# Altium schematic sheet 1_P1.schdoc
size 309 x 223 mm; Symbol: Sheet-Symbol_A4; Device: Sheet-Symbol_A4; @Page Name: P1; @Create Date: 2023-03-08; @Page Count: 2; @Page No: 1; @Project Name: flatbox; @Schematic Name: Schematic1; @Update Date: 2023-03-20; Company: 嘉立创EDA; Page Size: A4; Version: V1.0
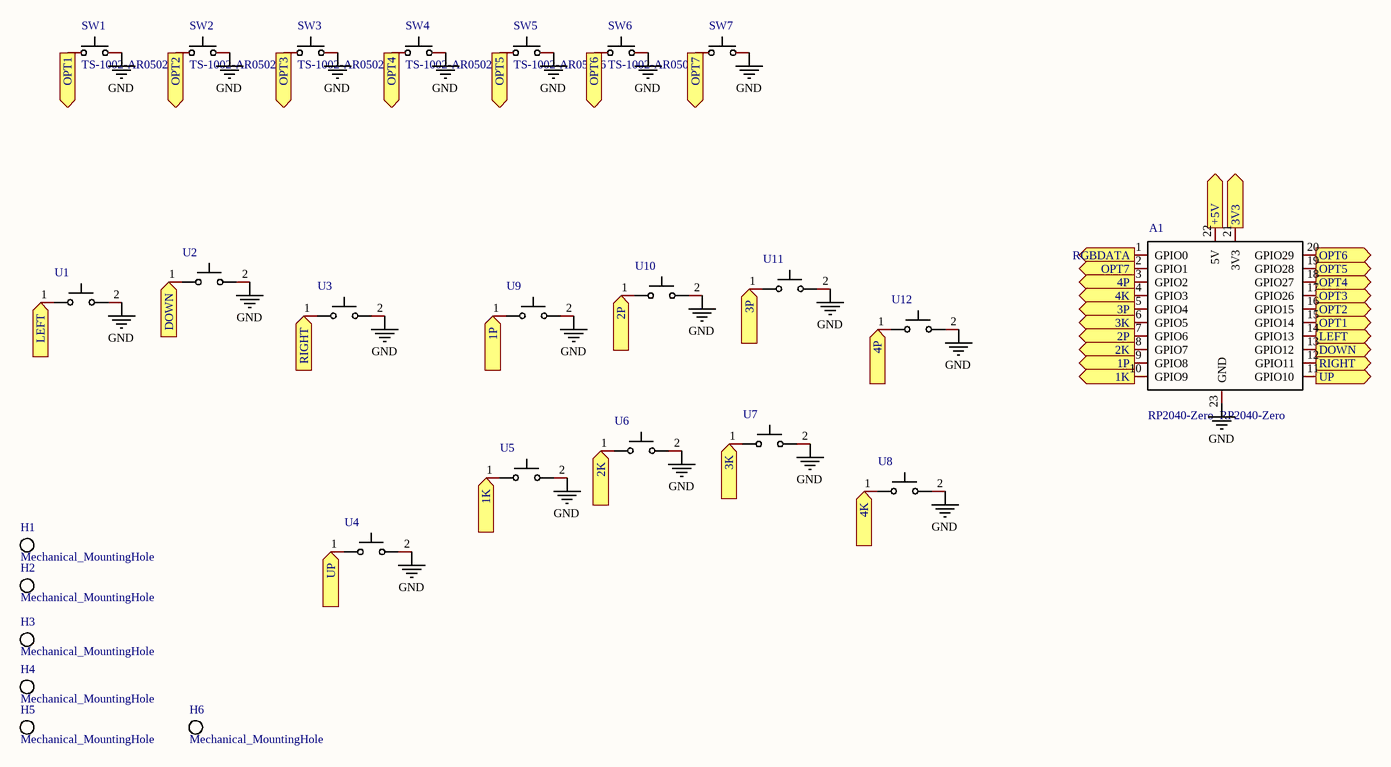
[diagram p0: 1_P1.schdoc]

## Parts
A1  RP2040-Zero_RP2040-Zero  [RP2040-Zero:RP2040-Zero]
H1  Mechanical_MountingHole  [MountingHole:MountingHole_6.4mm_M6]
H2  Mechanical_MountingHole  [MountingHole:MountingHole_6.4mm_M6]
H3  Mechanical_MountingHole  [MountingHole:MountingHole_6.4mm_M6]
H4  Mechanical_MountingHole  [MountingHole:MountingHole_6.4mm_M6]
H5  Mechanical_MountingHole  [MountingHole:MountingHole_6.4mm_M6]
H6  Mechanical_MountingHole  [MountingHole:MountingHole_6.4mm_M6]
SW1  TS-1002-AR05026  [SW-TH_4P-L6.0-W6.0-P4.50-LS6.5]
SW2  TS-1002-AR05026  [SW-TH_4P-L6.0-W6.0-P4.50-LS6.5]
SW3  TS-1002-AR05026  [SW-TH_4P-L6.0-W6.0-P4.50-LS6.5]
SW4  TS-1002-AR05026  [SW-TH_4P-L6.0-W6.0-P4.50-LS6.5]
SW5  TS-1002-AR05026  [SW-TH_4P-L6.0-W6.0-P4.50-LS6.5]
SW6  TS-1002-AR05026  [SW-TH_4P-L6.0-W6.0-P4.50-LS6.5]
SW7  TS-1002-AR05026  [SW-TH_4P-L6.0-W6.0-P4.50-LS6.5]  (value not drawn)
U1  CPG135001D02  [Kailh_socket_MX-ChocV1]  (value not drawn)
U2  CPG135001D02  [Kailh_socket_MX-ChocV1]  (value not drawn)
U3  CPG135001D02  [Kailh_socket_MX-ChocV1]  (value not drawn)
U4  CPG135001D02  [Kailh_socket_MX-ChocV1]  (value not drawn)
U5  CPG135001D02  [Kailh_socket_MX-ChocV1]  (value not drawn)
U6  CPG135001D02  [Kailh_socket_MX-ChocV1]  (value not drawn)
U7  CPG135001D02  [Kailh_socket_MX-ChocV1]  (value not drawn)
U8  CPG135001D02  [Kailh_socket_MX-ChocV1]  (value not drawn)
U9  CPG135001D02  [Kailh_socket_MX-ChocV1]  (value not drawn)
U10  CPG135001D02  [Kailh_socket_MX-ChocV1]  (value not drawn)
U11  CPG135001D02  [Kailh_socket_MX-ChocV1]  (value not drawn)
U12  CPG135001D02  [Kailh_socket_MX-ChocV1]  (value not drawn)

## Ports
1K (in), 1K (out), 1P (in), 1P (out), 2K (in), 2K (out), 2P (in), 2P (out), 3K (in), 3K (out), 3P (in), 3P (out), 3V3 (out), 4K (in), 4K (out), 4P (in), 4P (out), +5V (out), DOWN (in), DOWN (out), LEFT (in), LEFT (out), OPT1 (out), OPT2 (out), OPT3 (out), OPT4 (out), OPT5 (out), OPT6 (out), OPT7 (out), RGBDATA (out), RIGHT (in), RIGHT (out), UP (in), UP (out)

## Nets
GND: A1.23(GND) SW1.2 SW2.2 SW3.2 SW4.2 SW5.2 SW6.2 SW7.2 U1.2 U2.2 U3.2 U4.2 U5.2 U6.2 U7.2 U8.2 U9.2 U10.2 U11.2 U12.2
1K: A1.10(GPIO9) U5.1 ; port 1K
1P: A1.9(GPIO8) U9.1 ; port 1P
2K: A1.8(GPIO7) U6.1 ; port 2K
2P: A1.7(GPIO6) U10.1 ; port 2P
3K: A1.6(GPIO5) U7.1 ; port 3K
3P: A1.5(GPIO4) U11.1 ; port 3P
3V3: A1.21(3V3) ; port 3V3
4K: A1.4(GPIO3) U8.1 ; port 4K
4P: A1.3(GPIO2) U12.1 ; port 4P
+5V: A1.22(5V) ; port +5V
DOWN: A1.13(GPIO12) U2.1 ; port DOWN
LEFT: A1.14(GPIO13) U1.1 ; port LEFT
OPT1: A1.15(GPIO14) SW1.1 ; port OPT1
OPT2: A1.16(GPIO15) SW2.1 ; port OPT2
OPT3: A1.17(GPIO26) SW3.1 ; port OPT3
OPT4: A1.18(GPIO27) SW4.1 ; port OPT4
OPT5: A1.19(GPIO28) SW5.1 ; port OPT5
OPT6: A1.20(GPIO29) SW6.1 ; port OPT6
OPT7: A1.2(GPIO1) SW7.1 ; port OPT7
RGBDATA: A1.1(GPIO0) ; port RGBDATA
RIGHT: A1.12(GPIO11) U3.1 ; port RIGHT
UP: A1.11(GPIO10) U4.1 ; port UP

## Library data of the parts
A1 = RP2040-Zero_RP2040-Zero: Add into BOM: yes
H1-H6 = Mechanical_MountingHole: Add into BOM: yes
SW1-SW7 = TS-1002-AR05026: 触点电流:50mA;额定电压(DC):12V;绝缘电阻:100MΩ;电路结构:单刀单掷;安装方式:直插;按钮形状:圆形按钮;按钮/盖帽颜色:黑色;作用力:260gf@±50gf;机械寿命:100000;工作温度:-30℃~+80℃;引脚样式:PC引脚;开关长度:6mm;开关宽度:6mm;开关高度:5mm;带支架:否;; Manufacturer: XUNPU(讯普); Add into BOM: yes; Contact Current: 50mA; Voltage Rating (DC): 12V; Insulation Resistance: 100MΩ; Circuit: 单刀单掷; Actuator Style: 圆形按钮; Actuator/Cap Color: 黑色; Mechanical Life: 100000; Pin Style: PC引脚; Switch Length: 6mm; Switch Height: 5mm; Strike Gundam: 否; Value: SW_Push; Mounting Sytle: 立贴
U1-U12 = CPG135001D02: Add into BOM: yes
